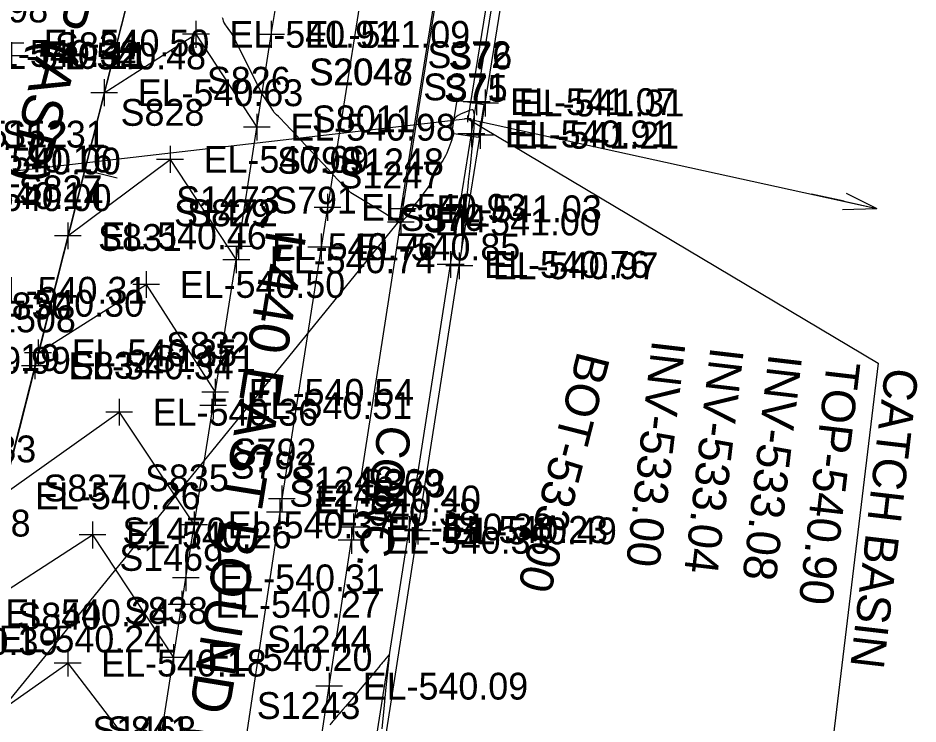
# Model space of a CAD drawing. Extents: x 1724534 to 1727318, y 657156 to 660047.
# Drawn here: x 1725578 to 1725712.3, y 659391.1 to 659496.3 of the extents above; entities that cross this region are included whole.
import ezdxf

# ---------------------------------------------------------------- set-up
doc = ezdxf.new("R2010")
doc.units = 0
for name, color, linetype in [('SURVEY - CENTERLINE - Preliminary', 7, 'Continuous'), ('SURVEY - CENTERLINE - Preliminary Text', 7, 'Continuous'), ('SURVEY - CONTOURS - Index with Text', 7, 'Continuous'), ('SURVEY - CONTOURS - Intermediate with optional Text', 7, 'Continuous'), ('SURVEY - DRAINAGE - Area Shapes', 7, 'Continuous'), ('SURVEY - DRAINAGE - Storm Sewer', 7, 'Continuous'), ('SURVEY - DRAINAGE - Storm Sewer - Points - Numbers', 7, 'Continuous'), ('SURVEY - DRAINAGE - Storm Sewer Text', 7, 'Continuous'), ('SURVEY - DTM - Breaklines', 7, 'Continuous'), ('SURVEY - DTM - Breaklines - Points - Elevations', 7, 'Continuous'), ('SURVEY - DTM - Breaklines - Points - Locators', 7, 'Continuous'), ('SURVEY - DTM - Breaklines - Points - Numbers', 7, 'Continuous'), ('SURVEY - MISCELLANEOUS - Bottom of MH and CB', 7, 'Continuous'), ('SURVEY - MISCELLANEOUS - Bottom of MH and CB - Points - Numbers', 7, 'Continuous'), ('SURVEY - TRAFFIC CONTROL - Pavement Marking - Points - Elevations', 7, 'Continuous'), ('SURVEY - TRAFFIC CONTROL - Pavement Marking - Points - Locators', 7, 'Continuous'), ('SURVEY - TRAFFIC CONTROL - Pavement Marking - Points - Numbers', 7, 'Continuous'), ('SURVEY - TRAFFIC CONTROL - Pavement Marking with Text', 7, 'Continuous'), ('SURVEY - TRANSPORTATION - Features', 7, 'Continuous'), ('SURVEY - TRANSPORTATION - Features - Points - Elevations', 7, 'Continuous'), ('SURVEY - TRANSPORTATION - Features - Points - Locators', 7, 'Continuous'), ('SURVEY - TRANSPORTATION - Features - Points - Numbers', 7, 'Continuous'), ('SURVEY - TRANSPORTATION - Features Text', 7, 'Continuous'), ('SURVEY - TRANSPORTATION - Roads', 7, 'Continuous'), ('SURVEY - TRANSPORTATION - Roads - Points - Elevations', 7, 'Continuous'), ('SURVEY - TRANSPORTATION - Roads - Points - Locators', 7, 'Continuous'), ('SURVEY - TRANSPORTATION - Roads - Points - Numbers', 7, 'Continuous'), ('SURVEY - TRANSPORTATION - Roads Text', 7, 'Continuous')]:
    doc.layers.add(name, color=color, linetype=linetype)

msp = doc.modelspace()

# ---------------------------------------------------------------- linework, layer by layer
at = {"layer": 'SURVEY - CENTERLINE - Preliminary'}
msp.add_line((1725628.75, 659634.75), (1725510.02, 659165.78), dxfattribs=at)
msp.add_line((1725628.75, 659634.75), (1725510.02, 659165.78), dxfattribs=at)
msp.add_line((1725628.75, 659634.75), (1725510.02, 659165.78), dxfattribs=at)
at = {"layer": 'SURVEY - CENTERLINE - Preliminary Text'}
msp.add_line((1725587.98, 659473.71), (1725592.83, 659472.48), dxfattribs=at)
at = {"layer": 'SURVEY - CONTOURS - Index with Text'}
msp.add_lwpolyline([(1725632.32, 659390.38), (1725632.68, 659393.91), (1725632.85, 659395.55), (1725632.9, 659396.08), (1725633.36, 659400.66), (1725633.44, 659401.5), (1725632.69, 659400.6), (1725632.58, 659400.47), (1725632.48, 659400.35), (1725632.39, 659400.25), (1725632.19, 659400), (1725632.06, 659399.85), (1725631.83, 659399.58), (1725631.5, 659399.18), (1725631.07, 659398.67), (1725629.31, 659396.57), (1725628.85, 659396.03), (1725628.41, 659395.51), (1725626.87, 659393.72), (1725626.49, 659393.27), (1725626.17, 659392.9), (1725625.92, 659392.61), (1725625.73, 659392.39), (1725625.33, 659391.91), (1725625.17, 659391.72), (1725624.98, 659391.5), (1725624.76, 659391.25), (1725624.52, 659390.97)], dxfattribs=at)
at = {"layer": 'SURVEY - CONTOURS - Intermediate with optional Text'}
msp.add_lwpolyline([(1725644.17, 659461.51), (1725644.39, 659463.89), (1725644.45, 659464.45), (1725644.53, 659465.15), (1725644.56, 659465.46), (1725644.66, 659466.45), (1725644.87, 659468.68), (1725644.93, 659469.19), (1725644.97, 659469.62), (1725645.01, 659469.98), (1725645.15, 659471.16), (1725645.23, 659471.91), (1725645.44, 659473.89), (1725645.49, 659474.32), (1725645.54, 659474.76), (1725645.73, 659476.38), (1725645.78, 659476.8), (1725645.87, 659477.5), (1725645.97, 659478.47), (1725646, 659478.75), (1725646.02, 659479.07), (1725646.03, 659479.43), (1725646.05, 659479.84), (1725646.09, 659481.83), (1725645.95, 659482.51), (1725645.87, 659482.61), (1725645.7, 659482.64), (1725645.44, 659482.58), (1725645.1, 659482.45), (1725644.04, 659481.98), (1725643.68, 659481.8), (1725643.39, 659481.61), (1725643.17, 659481.41), (1725643.02, 659481.19), (1725642.71, 659480.59), (1725642.62, 659480.36), (1725642.57, 659480.14), (1725642.57, 659479.91), (1725642.61, 659479.69), (1725642.79, 659479.09), (1725642.82, 659478.84), (1725642.8, 659478.53), (1725642.72, 659478.18), (1725642.58, 659477.76), (1725642.14, 659476.59), (1725641.96, 659476.17), (1725641.78, 659475.78), (1725641.58, 659475.41), (1725641.37, 659475.07), (1725640.79, 659474.22), (1725640.58, 659473.9), (1725640.4, 659473.58), (1725640.23, 659473.26), (1725640.09, 659472.94), (1725639.73, 659472.08), (1725639.57, 659471.74), (1725639.34, 659471.35), (1725639.05, 659470.92), (1725638.7, 659470.45), (1725637.69, 659469.14), (1725637.35, 659468.7), (1725637.09, 659468.35), (1725636.91, 659468.09), (1725636.82, 659467.93), (1725636.68, 659467.62), (1725636.6, 659467.49), (1725636.49, 659467.34), (1725636.35, 659467.15), (1725636.17, 659466.94), (1725635.31, 659465.99), (1725635.18, 659465.83), (1725635.07, 659465.69), (1725634.76, 659465.91), (1725634.64, 659465.99), (1725634.1, 659466.33), (1725631.96, 659467.66), (1725631.03, 659468.23), (1725627.68, 659470.28), (1725627.34, 659470.58), (1725626.66, 659471.26), (1725625.63, 659472.32), (1725624.26, 659473.77), (1725620.16, 659478.15), (1725618.8, 659479.6), (1725617.8, 659480.66), (1725617.15, 659481.34), (1725616.86, 659481.63), (1725616.56, 659481.89), (1725616.43, 659482.03), (1725616.25, 659482.26), (1725616.03, 659482.57), (1725615.76, 659482.97), (1725614.41, 659485.05), (1725610.17, 659493.56), (1725610.08, 659493.73), (1725609.95, 659493.93), (1725609.8, 659494.15), (1725609.63, 659494.4), (1725609.12, 659495.08), (1725608.95, 659495.32), (1725608.82, 659495.53), (1725608.73, 659495.7), (1725608.68, 659495.84), (1725608.61, 659496.16), (1725608.53, 659496.34)], dxfattribs=at)
at = {"layer": 'SURVEY - DRAINAGE - Area Shapes'}
msp.add_lwpolyline([(1725457.87, 659006.78), (1725413.86, 659016.26), (1725297.61, 659050.84), (1725314.04, 659296.61), (1725386.76, 659493.9), (1725483.4, 659755.23), (1725623.95, 659732.7), (1725676.22, 659724.33), (1725634.82, 659466.02), (1725543.32, 659353.72), (1725499.68, 659185.92), (1725479.09, 659106.74)], close=True, dxfattribs=at)
at = {"layer": 'SURVEY - DRAINAGE - Storm Sewer'}
for p, q in [((1725684.98, 659727.99), (1725645.11, 659481.28)), ((1725645.11, 659481.28), (1725564.93, 659472.02)), ((1725645.11, 659481.28), (1725645.11, 659481.28)), ((1725645.11, 659481.28), (1725645.11, 659481.28)), ((1725645.11, 659481.28), (1725706.14, 659467.93)), ((1725701.26, 659469), (1725696.37, 659470.07)), ((1725701.53, 659470.22), (1725706.14, 659467.93)), ((1725700.99, 659467.78), (1725706.14, 659467.93)), ((1725701.26, 659469), (1725706.14, 659467.93)), ((1725701.26, 659469), (1725706.14, 659467.93))]:
    msp.add_line(p, q, dxfattribs=at)
msp.add_lwpolyline([(1725646.69, 659478.49), (1725642.74, 659479.13), (1725643.53, 659484.06), (1725647.48, 659483.43), (1725646.69, 659478.49)], dxfattribs=at)
msp.add_lwpolyline([(1725646.69, 659478.49), (1725642.74, 659479.13), (1725643.53, 659484.06), (1725647.48, 659483.43), (1725646.69, 659478.49)], dxfattribs=at)
at = {"layer": 'SURVEY - DRAINAGE - Storm Sewer Text'}
msp.add_lwpolyline([(1725645.11, 659481.28), (1725706.33, 659444.86), (1725699.43, 659387.9)], dxfattribs=at)
at = {"layer": 'SURVEY - DTM - Breaklines'}
msp.add_lwpolyline([(1725623.6, 659326.2), (1725625.6, 659340.96), (1725631.47, 659380.35), (1725637.66, 659419.87), (1725643.84, 659459.39), (1725646.93, 659478.84), (1725647.71, 659483.65), (1725654.06, 659523.1), (1725660.55, 659562.56), (1725667, 659602.05), (1725673.28, 659641.55), (1725679.66, 659681.01), (1725686.77, 659724.7), (1725687.76, 659730.9), (1725694.15, 659770.38), (1725697.5, 659791.07)], dxfattribs=at)
at = {"layer": 'SURVEY - DTM - Breaklines - Points - Locators'}
for p, q in [((1725647.71, 659485.65), (1725647.71, 659481.65)), ((1725649.71, 659483.65), (1725645.71, 659483.65)), ((1725646.93, 659480.84), (1725646.93, 659476.84)), ((1725648.93, 659478.84), (1725644.93, 659478.84)), ((1725643.84, 659461.39), (1725643.84, 659457.39)), ((1725645.84, 659459.39), (1725641.84, 659459.39)), ((1725637.66, 659421.87), (1725637.66, 659417.87)), ((1725639.66, 659419.87), (1725635.66, 659419.87))]:
    msp.add_line(p, q, dxfattribs=at)
at = {"layer": 'SURVEY - MISCELLANEOUS - Bottom of MH and CB'}
for p, q in [((1725645.11, 659480.78), (1725645.11, 659481.78)), ((1725645.61, 659481.28), (1725644.61, 659481.28)), ((1725645.11, 659481.28), (1725645.11, 659481.28)), ((1725645.11, 659481.28), (1725645.11, 659481.28))]:
    msp.add_line(p, q, dxfattribs=at)
at = {"layer": 'SURVEY - TRAFFIC CONTROL - Pavement Marking - Points - Locators'}
for p, q in [((1725604.56, 659495.89), (1725604.56, 659491.89)), ((1725606.56, 659493.89), (1725602.56, 659493.89)), ((1725590.87, 659487.18), (1725590.87, 659483.18)), ((1725592.87, 659485.18), (1725588.87, 659485.18)), ((1725613.64, 659482.04), (1725613.64, 659478.04)), ((1725615.64, 659480.04), (1725611.64, 659480.04)), ((1725600.7, 659477.25), (1725600.7, 659473.25)), ((1725602.7, 659475.25), (1725598.7, 659475.25)), ((1725624.18, 659470.1), (1725624.18, 659466.1)), ((1725626.18, 659468.1), (1725622.18, 659468.1)), ((1725585.44, 659465.85), (1725585.44, 659461.85)), ((1725623.25, 659464.18), (1725623.25, 659460.18)), ((1725587.44, 659463.85), (1725583.44, 659463.85)), ((1725610.58, 659462.28), (1725610.58, 659458.28)), ((1725625.25, 659462.18), (1725621.25, 659462.18)), ((1725612.58, 659460.28), (1725608.58, 659460.28)), ((1725597.14, 659458.61), (1725597.14, 659454.61)), ((1725599.14, 659456.61), (1725595.14, 659456.61)), ((1725581.01, 659448.41), (1725581.01, 659444.41)), ((1725583.01, 659446.41), (1725579.01, 659446.41)), ((1725607.43, 659442.53), (1725607.43, 659438.53)), ((1725609.43, 659440.53), (1725605.43, 659440.53)), ((1725593.11, 659439.56), (1725593.11, 659435.56)), ((1725595.11, 659437.56), (1725591.11, 659437.56)), ((1725617.38, 659426.63), (1725617.38, 659422.63)), ((1725619.38, 659424.63), (1725615.38, 659424.63)), ((1725617.07, 659424.66), (1725617.07, 659420.66)), ((1725604.3, 659422.77), (1725604.3, 659418.77)), ((1725619.07, 659422.66), (1725615.07, 659422.66)), ((1725589.14, 659421.27), (1725589.14, 659417.27)), ((1725606.3, 659420.77), (1725602.3, 659420.77)), ((1725591.14, 659419.27), (1725587.14, 659419.27)), ((1725585.43, 659402.17), (1725585.43, 659398.17)), ((1725601.21, 659403.01), (1725601.21, 659399.01)), ((1725603.21, 659401.01), (1725599.21, 659401.01)), ((1725587.43, 659400.17), (1725583.43, 659400.17))]:
    msp.add_line(p, q, dxfattribs=at)
at = {"layer": 'SURVEY - TRAFFIC CONTROL - Pavement Marking with Text'}
for points in [[(1725677.08, 659796.31), (1725674.76, 659781.99), (1725662.24, 659705.03), (1725649.13, 659624.1), (1725636.68, 659547.11), (1725636.37, 659545.14), (1725624.18, 659468.1), (1725623.25, 659462.18), (1725617.38, 659424.63), (1725617.07, 659422.66), (1725605.51, 659345.52), (1725605.22, 659343.54), (1725602.95, 659328.1)], [(1725590.87, 659485.18), (1725604.56, 659493.89), (1725613.64, 659480.04)], [(1725585.44, 659463.85), (1725600.7, 659475.25), (1725610.58, 659460.28)], [(1725581.01, 659446.41), (1725597.14, 659456.61), (1725607.43, 659440.53)], [(1725575.57, 659425.09), (1725593.11, 659437.56), (1725604.3, 659420.77)], [(1725571.12, 659407.65), (1725589.14, 659419.27), (1725601.21, 659401.01)], [(1725565.73, 659386.32), (1725585.43, 659400.17), (1725598.45, 659383.22)]]:
    msp.add_lwpolyline(points, dxfattribs=at)
at = {"layer": 'SURVEY - TRANSPORTATION - Features'}
msp.add_lwpolyline([(1725622.21, 659326.39), (1725624.29, 659341.14), (1725630.17, 659380.56), (1725636.35, 659420.08), (1725642.55, 659459.59), (1725645.64, 659479.05), (1725646.42, 659483.85), (1725652.78, 659523.31), (1725659.27, 659562.77), (1725665.72, 659602.26), (1725672, 659641.75), (1725678.37, 659681.22), (1725685.48, 659724.91), (1725686.48, 659731.1), (1725692.86, 659770.59), (1725696.22, 659791.27)], dxfattribs=at)
at = {"layer": 'SURVEY - TRANSPORTATION - Features - Points - Locators'}
for p, q in [((1725646.42, 659485.85), (1725646.42, 659481.85)), ((1725648.42, 659483.85), (1725644.42, 659483.85)), ((1725645.64, 659481.05), (1725645.64, 659477.05)), ((1725647.64, 659479.05), (1725643.64, 659479.05)), ((1725642.55, 659461.59), (1725642.55, 659457.59)), ((1725644.55, 659459.59), (1725640.55, 659459.59)), ((1725636.35, 659422.08), (1725636.35, 659418.08)), ((1725638.35, 659420.08), (1725634.35, 659420.08))]:
    msp.add_line(p, q, dxfattribs=at)
at = {"layer": 'SURVEY - TRANSPORTATION - Roads'}
for points in [[(1725614.21, 659327.48), (1725617.73, 659353.24), (1725618.02, 659355.22), (1725622.92, 659386.84), (1725624.43, 659396.73), (1725627.75, 659418.47), (1725628.06, 659420.45), (1725635.11, 659465.91), (1725635.41, 659467.88), (1725643.91, 659521.21), (1725646.49, 659537), (1725655.84, 659594.23), (1725667.29, 659665.3), (1725672.1, 659694.9), (1725680.45, 659746.21), (1725687.95, 659792.61)], [(1725590.71, 659328.92), (1725598.17, 659381.25), (1725598.45, 659383.22), (1725602.44, 659408.92), (1725603.05, 659412.87), (1725607.12, 659438.55), (1725610.58, 659460.28), (1725610.89, 659462.25), (1725615.78, 659493.88), (1725619.05, 659513.61), (1725619.37, 659515.58), (1725622.79, 659537.31), (1725623.11, 659539.29), (1725628.25, 659570.87), (1725628.56, 659572.84), (1725632.34, 659596.54), (1725632.66, 659598.52), (1725636.55, 659622.19)], [(1725624.67, 659618.96), (1725609.02, 659556.91), (1725594.32, 659498.75), (1725580.52, 659444.47), (1725570.13, 659403.77), (1725561.33, 659368.86), (1725557.93, 659355.29), (1725547.17, 659312.62), (1725545.21, 659304.87), (1725533.45, 659258.34), (1725527.51, 659235.09)]]:
    msp.add_lwpolyline(points, dxfattribs=at)
at = {"layer": 'SURVEY - TRANSPORTATION - Roads - Points - Locators'}
for p, q in [((1725615.78, 659495.88), (1725615.78, 659491.88)), ((1725617.78, 659493.88), (1725613.78, 659493.88)), ((1725578.87, 659492.59), (1725574.87, 659492.59)), ((1725578.38, 659490.66), (1725574.38, 659490.66)), ((1725635.41, 659469.88), (1725635.41, 659465.88)), ((1725637.41, 659467.88), (1725633.41, 659467.88)), ((1725635.11, 659467.91), (1725635.11, 659463.91)), ((1725637.11, 659465.91), (1725633.11, 659465.91)), ((1725610.89, 659464.25), (1725610.89, 659460.25)), ((1725612.89, 659462.25), (1725608.89, 659462.25)), ((1725610.58, 659462.28), (1725610.58, 659458.28)), ((1725612.58, 659460.28), (1725608.58, 659460.28)), ((1725580.52, 659446.47), (1725580.52, 659442.47)), ((1725582.52, 659444.47), (1725578.52, 659444.47)), ((1725607.12, 659440.55), (1725607.12, 659436.55)), ((1725609.12, 659438.55), (1725605.12, 659438.55)), ((1725628.06, 659422.45), (1725628.06, 659418.45)), ((1725630.06, 659420.45), (1725626.06, 659420.45)), ((1725627.75, 659420.47), (1725627.75, 659416.47)), ((1725629.75, 659418.47), (1725625.75, 659418.47)), ((1725603.05, 659414.87), (1725603.05, 659410.87)), ((1725605.05, 659412.87), (1725601.05, 659412.87)), ((1725602.44, 659410.92), (1725602.44, 659406.92)), ((1725604.44, 659408.92), (1725600.44, 659408.92)), ((1725624.43, 659398.73), (1725624.43, 659394.73)), ((1725626.43, 659396.73), (1725622.43, 659396.73))]:
    msp.add_line(p, q, dxfattribs=at)

# ---------------------------------------------------------------- texts
at = {"layer": 'SURVEY - DRAINAGE - Storm Sewer - Points - Numbers'}
for s, p in [('S2048', (1725621.44, 659486.28)), ('S2047', (1725621.54, 659486.28)), ('S5112', (1725569.93, 659477.02)), ('S5231', (1725575.64, 659477.01))]:
    msp.add_text(s, height=4, dxfattribs=at).set_placement(p)
at = {"layer": 'SURVEY - DRAINAGE - Storm Sewer Text'}
for s, p in [('INV-533.00', (1725672.63, 659448.42)), ('INV-533.04', (1725681.32, 659447.4)), ('INV-533.08', (1725690.01, 659446.38)), ('TOP-540.90', (1725698.7, 659445.36)), ('CATCH BASIN', (1725707.39, 659444.34))]:
    msp.add_text(s, height=5, rotation=263.3153, dxfattribs=at).set_placement(p)
at = {"layer": 'SURVEY - DTM - Breaklines - Points - Elevations'}
for s, p in [('EL-540.32', (1725571.46, 659489.04)), ('EL-541.31', (1725652.71, 659481.65)), ('EL-541.21', (1725651.93, 659476.84)), ('EL-540.16', (1725567.45, 659473.31)), ('EL-540.14', (1725566.08, 659467.84)), ('EL-540.97', (1725648.84, 659457.39)), ('EL-540.19', (1725559.6, 659443.71)), ('EL-540.49', (1725642.66, 659417.87))]:
    msp.add_text(s, height=4, dxfattribs=at).set_placement(p)
at = {"layer": 'SURVEY - DTM - Breaklines - Points - Numbers'}
for s, p in [('S76', (1725642.21, 659488.65)), ('S75', (1725641.54, 659483.84)), ('S74', (1725638.45, 659464.39)), ('S73', (1725632.28, 659424.87))]:
    msp.add_text(s, height=4, dxfattribs=at).set_placement(p)
at = {"layer": 'SURVEY - MISCELLANEOUS - Bottom of MH and CB'}
msp.add_text('BOT-533.00', height=5, rotation=255.7596, dxfattribs=at).set_placement((1725661.5, 659446.81))
at = {"layer": 'SURVEY - MISCELLANEOUS - Bottom of MH and CB - Points - Numbers'}
msp.add_text('S8011', height=4, dxfattribs=at).set_placement((1725621.85, 659479.28))
at = {"layer": 'SURVEY - TRAFFIC CONTROL - Pavement Marking - Points - Elevations'}
for s, p in [('EL-540.91', (1725609.56, 659491.89)), ('EL-540.63', (1725595.87, 659483.18)), ('EL-540.98', (1725618.64, 659478.04)), ('EL-540.69', (1725605.7, 659473.25)), ('EL-540.93', (1725629.18, 659466.1)), ('EL-540.46', (1725590.44, 659461.85)), ('EL-540.85', (1725628.25, 659460.18)), ('EL-540.74', (1725615.58, 659458.28)), ('EL-540.50', (1725602.14, 659454.61)), ('EL-540.35', (1725586.01, 659444.41)), ('EL-540.54', (1725612.43, 659438.53)), ('EL-540.36', (1725598.11, 659435.56)), ('EL-540.26', (1725580.57, 659423.09)), ('EL-540.40', (1725622.38, 659422.63)), ('EL-540.38', (1725622.07, 659420.66)), ('EL-540.37', (1725609.3, 659418.77)), ('EL-540.26', (1725594.14, 659417.27)), ('EL-540.24', (1725576.12, 659405.65)), ('EL-540.18', (1725590.43, 659398.17)), ('EL-540.20', (1725606.21, 659399.01))]:
    msp.add_text(s, height=4, dxfattribs=at).set_placement(p)
at = {"layer": 'SURVEY - TRAFFIC CONTROL - Pavement Marking - Points - Numbers'}
for s, p in [('S824', (1725583.53, 659490.18)), ('S826', (1725606.19, 659485.04)), ('S828', (1725593.32, 659480.25)), ('S790', (1725616.67, 659473.1)), ('S827', (1725578.11, 659468.85)), ('S791', (1725616.07, 659467.18)), ('S829', (1725603.23, 659465.28)), ('S831', (1725589.96, 659461.61)), ('S830', (1725573.5, 659451.41)), ('S832', (1725600.1, 659445.53)), ('S834', (1725585.77, 659442.56)), ('S833', (1725568.24, 659430.09)), ('S792', (1725610.04, 659429.63)), ('S793', (1725609.73, 659427.66)), ('S835', (1725596.97, 659425.77)), ('S837', (1725581.8, 659424.27)), ('S840', (1725577.92, 659405.17)), ('S838', (1725593.83, 659406.01)), ('S841', (1725591.27, 659388.22))]:
    msp.add_text(s, height=4, dxfattribs=at).set_placement(p)
at = {"layer": 'SURVEY - TRANSPORTATION - Features - Points - Elevations'}
for s, p in [('EL-540.11', (1725572.67, 659488.73)), ('EL-541.07', (1725651.42, 659481.85)), ('EL-540.91', (1725650.64, 659477.05)), ('EL-540.00', (1725568.67, 659473)), ('EL-540.00', (1725567.29, 659467.54)), ('EL-540.76', (1725647.55, 659457.59)), ('EL-539.99', (1725561.23, 659443.3)), ('EL-540.08', (1725555.21, 659419.03)), ('EL-540.23', (1725641.35, 659418.08))]:
    msp.add_text(s, height=4, dxfattribs=at).set_placement(p)
at = {"layer": 'SURVEY - TRANSPORTATION - Features - Points - Numbers'}
for s, p in [('S372', (1725639.09, 659488.85)), ('S371', (1725638.46, 659484.05)), ('S370', (1725635.04, 659464.59)), ('S369', (1725629, 659425.08))]:
    msp.add_text(s, height=4, dxfattribs=at).set_placement(p)
at = {"layer": 'SURVEY - TRANSPORTATION - Features Text'}
msp.add_text('CONC.', height=5, rotation=261.1064, dxfattribs=at).set_placement((1725631.85, 659435.87))
at = {"layer": 'SURVEY - TRANSPORTATION - Roads - Points - Elevations'}
for s, p in [('EL-541.09', (1725620.78, 659491.88)), ('EL-540.50', (1725581.87, 659490.59)), ('EL-540.48', (1725581.38, 659488.66)), ('EL-541.03', (1725640.41, 659465.88)), ('EL-541.00', (1725640.11, 659463.91)), ('EL-540.76', (1725615.89, 659460.25)), ('EL-540.74', (1725615.58, 659458.28)), ('EL-540.31', (1725572.62, 659453.74)), ('EL-540.30', (1725572.13, 659451.8)), ('EL-540.34', (1725585.52, 659442.47)), ('EL-540.51', (1725612.12, 659436.55)), ('EL-540.38', (1725633.06, 659418.45)), ('EL-540.35', (1725632.75, 659416.47)), ('EL-540.31', (1725608.05, 659410.87)), ('EL-540.27', (1725607.44, 659406.92)), ('EL-540.39', (1725559.36, 659401.39)), ('EL-540.24', (1725575.13, 659401.77)), ('EL-540.09', (1725629.43, 659394.73))]:
    msp.add_text(s, height=4, dxfattribs=at).set_placement(p)
at = {"layer": 'SURVEY - TRANSPORTATION - Roads - Points - Numbers'}
for s, p in [('S1398', (1725567.05, 659495.66)), ('S1248', (1725626.08, 659472.88)), ('S1247', (1725625.82, 659470.91)), ('S1473', (1725601.6, 659467.25)), ('S1472', (1725601.29, 659465.28)), ('S1508', (1725571.18, 659449.47)), ('S1471', (1725597.99, 659443.55)), ('S1246', (1725618.66, 659425.45)), ('S1245', (1725618.47, 659423.47)), ('S1470', (1725593.59, 659417.87)), ('S1469', (1725593.13, 659413.92)), ('S1244', (1725615.14, 659401.73)), ('S1243', (1725613.63, 659391.84)), ('S1468', (1725589.12, 659388.22))]:
    msp.add_text(s, height=4, dxfattribs=at).set_placement(p)
at = {"layer": 'SURVEY - TRANSPORTATION - Roads Text'}
for s, rotation, p in [('I-440 EASTBOUND EXIT RAMP (ASP)', 255.7467, (1725610.5, 659607.82)), ('I-440 EAST BOUND (ASP.)', 260.8169, (1725615.12, 659464.93))]:
    msp.add_text(s, height=6, rotation=rotation, dxfattribs=at).set_placement(p)

doc.saveas('drawing.dxf')
